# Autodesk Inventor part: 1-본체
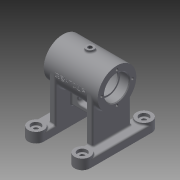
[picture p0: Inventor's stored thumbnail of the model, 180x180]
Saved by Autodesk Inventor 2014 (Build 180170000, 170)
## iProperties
Created: 2015-11
Part Number: 1-본체
Material: Generic
Document SubType Name: Modeling
Designer: test_24
Density: 1 g/cm^3
Appearance: Default
Author: test_24
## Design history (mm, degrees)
sketch "스케치1"
  geometry: L1 (-35, 25)-(35, 25); L2 (35, 25)-(35, 16); L3 (35, 0)-(-35, 0); L4 (-35, 16)-(-35, 25); L5 (-35, 16)-(-23, 16); L6 (-23, 16)-(-23, 14); L7 (-23, 14)-(-21, 14); L8 (-21, 14)-(-21, 21); L9 (-21, 21)-(21, 21); L10 (21, 21)-(21, 14); L11 (21, 14)-(23, 14); L12 (23, 14)-(23, 16); L13 (23, 16)-(35, 16); 1 further point
  constraints: 26 end point, 8 parallel, 4 perpendicular, 2 vertical alignment, 1 horizontal, 1 midpoint
  dimensions: "d0" = 25 distance of L3.end L1.start; "d1" = 70 distance of L3.start L3.end; "d2" = 35 distance from line of point (0, 0) L4; "d3" = 32 diameter of L5 L3; "d4" = 28 diameter of L7 L3; "d5" = 42 diameter of L9 L3; "d6" = 28 diameter of L11 L3; "d7" = 32 diameter of L13 L3; "d8" = 12 distance between parallel lines of L6 L4; "d9" = 2 distance between parallel lines of L6 L8; "d10" = 42 distance between parallel lines of L8 L10; "d11" = 2 distance between parallel lines of L12 L10
revolve "회전1" sketch "스케치1" stored, may be unused: angle "d12" = 90 deg
node "작업 평면1"
sketch "스케치2"
  geometry: L1 (-40, -40)-(-40, 40); L2 (-20, 40)-(-20, -40); L3 (20, -40)-(20, 40); L4 (40, 40)-(40, -40); A1 r 10 centre (-30, -40) between (-20, -40) and (-40, -40); A2 r 10 centre (-30, 40) between (-40, 40) and (-20, 40); A3 r 10 centre (30, 40) between (20, 40) and (40, 40); A4 r 10 centre (30, -40) between (40, -40) and (20, -40); 1 further point
  constraints: 8 end point, 8 point on circle, 4 centre point, 3 equal radius, 3 tangent, 2 horizontal alignment, 2 parallel, 2 vertical alignment
  dimensions: "d14" = 80 distance between parallel lines of L4 L1; "d15" = 40 distance from line of L1 point (0, 0); "d16" = 20 distance between parallel lines of L4 L3; "d17" = 20 distance between parallel lines of L1 L2; "d22" = 10 radius of A4; "d23" = 80 distance of A3.centre A4.centre; "d36" = 40 vertical distance of A4.centre point (0, 0)
extrude "돌출1" join sketch "스케치2" distance "d26" = 10; taper "d27" = 0 deg
sketch "스케치3"
  geometry: L1 (40, -40)-(40, 40) reference; L2 (-40, 40)-(-40, -40) reference; C1 r 10 at (-30, -40); C2 r 10 at (-30, 40); C3 r 10 at (30, 40); A1 r 10 centre (-30, -40) between (-20, -40) and (-40, -40) reference; A2 r 10 centre (-30, 40) between (-40, 40) and (-20, 40) reference; A3 r 10 centre (30, 40) between (20, 40) and (40, 40) reference; A4 r 10 centre (30, -40) between (40, -40) and (20, -40) reference; 2 further points
  constraints: 4 coincident, 3 centre point, 3 tangent, 1 horizontal alignment, 2 other
extrude "돌출2" join sketch "스케치3" distance "d28" = 13; taper "d29" = 0 deg
node "스케치4"
sketch "스케치5"
  geometry: L1 (20, 40)-(20, -40) reference; L2 (-20, 40)-(-20, -40) reference; L3 (20, 25)-(28, 25); L4 (28, 25)-(28, -25); L5 (28, -25)-(20, -25); L6 (20, -25)-(20, 25); L7 (-20, 25)-(-28, 25); L8 (-28, 25)-(-28, -25); L9 (-28, -25)-(-20, -25); L10 (-20, -25)-(-20, 25); 1 further point
  constraints: 16 end point, 4 parallel, 2 horizontal, 2 perpendicular, 2 point on line
  dimensions: "d37" = 8 distance of L4.end L5.end; "d38" = 50 distance of L3.end L4.end; "d39" = 8 distance of L9.end L8.end; "d40" = 50 distance of L8.end L7.end; "d41" = 25 distance from line of point (0, 0) L3; "d42" = 25 distance from line of L7 point (0, 0)
extrude "돌출3" join sketch "스케치5" stored distance "d43" = 13; taper "d44" = 0 deg
sketch "스케치6"
  geometry: L1 (-20, -58)-(-20, 0) reference; L2 (20, -22.684)-(20, -45); L3 (20, -45)-(-20, -45); L4 (-20, -45)-(-20, -22.684); L5 (-20, -22.684)-(20, -22.684); L6 (20, -58)-(20, 0) reference; L7 (-35, -25)-(35, -25) reference; 1 further point
  constraints: 8 end point, 3 collinear, 1 parallel
  dimensions: "d104" = 20 distance between parallel lines of L7 L3; "d105" = 22.31618 distance between parallel lines of L3 L5
extrude "돌출4" join sketch "스케치6" stored distance "d47" = 8; taper "d48" = 0 deg
sketch "스케치8"
  geometry: C1 r 10 at (0, 0) reference; C2 r 10 at (0, 80) reference; C3 r 10 at (60, 80) reference; C4 r 10 at (60, 0) reference; 5 further points
  constraints: 4 coincident
hole "구멍1" sketch "스케치8" at (0, 80), (60, 80), (60, 0), (0, 0) diameter "d56" = 6; stored, may be unused: countersink angle "d60" = 90 deg, drill point angle "d62" = 118 deg; dims "d57" = 6, "d58" = 12, "d59" = 4, "d61" = 8
node "작업 평면3"
sketch "스케치11"
  geometry: C1 r 5 at (0, 0); 1 further point
  constraints: 1 centre point, 1 coincident
  dimensions: "d70" = 10 diameter of C1
extrude "돌출7" join sketch "스케치11" stored distance "d71" = 8; taper "d72" = 0 deg
sketch "스케치12"
  geometry: C1 r 5 at (0, 0) reference; 1 further point
  constraints: 1 coincident
hole "구멍2" sketch "스케치12" at (0, 0) diameter "d73" = 5.188; stored, may be unused: countersink angle "d77" = 90 deg, drill point angle "d79" = 118 deg; dims "d74" = 14, "d75" = 12, "d76" = 4, "d78" = 15
fillet "모깎기1" dims "d87" = 0.3
fillet "모깎기2" dims "d88" = 3
sketch "스케치14"
  geometry: C1 r 16 at (0, 0) reference; 4 further points
  constraints: 1 vertical alignment, 5 other
  dimensions: "d89" = 20 distance of C1.centre point (0, 20); "d92" = 360 deg dimension on C1.centre point (0, 20) (derived)
hole "구멍4" sketch "스케치14" at (0, 20), (-20, 0), (0, -20), (20, 0) diameter "d94" = 3.242; stored, may be unused: countersink angle "d98" = 90 deg, drill point angle "d100" = 118 deg; dims "d95" = 8, "d96" = 12, "d97" = 4, "d99" = 10
fillet "모깎기5" dims "d103" = 2
sketch "스케치15"
  geometry: L1 (-20, -24.678)-(20, -24.678) reference; L2 (-8, -35)-(8, -35); L3 (-8, -31.5)-(8, -31.5); L4 (8, -38.5)-(-8, -38.5); L5 (20, -68)-(40, -68) reference; L6 (-35, -21.621)-(-35, -18.379) reference; A1 r 3.5 centre (-8, -35) between (-8, -31.5) and (-8, -38.5); A2 r 3.5 centre (8, -35) between (8, -38.5) and (8, -31.5); 2 further points
  constraints: 8 end point, 4 point on circle, 4 tangent, 2 centre point, 2 parallel, 1 midpoint
  dimensions: "d106" = 3.5 radius of A2; "d107" = 33 distance from line of L5 point (0, -35); "d108" = 35 distance from line of L6 point (0, -35); "d109" = 16 distance of L2.end L2.start
extrude "돌출8" cut sketch "스케치15" distance "d110" = 8; taper "d111" = 0 deg
sketch "스케치16"
  geometry: L1 (0, 0)-(-24.249, -14); L2 (0, 0)-(-23.07, 0)
  constraints: 4 end point, 1 horizontal
  dimensions: "d112" = 28 distance of L1.start L1.end; "d113" = 30 deg angle of L2 L1
node "작업 평면4"
sketch "스케치17"
  geometry: C1 r 6 at (0, 0); 1 further point
  constraints: 1 centre point, 1 coincident
  dimensions: "d114" = 12 diameter of C1
extrude "돌출9" join sketch "스케치17" stored distance "d115" = 8; taper "d116" = 0 deg
sketch "스케치18"
  geometry: C1 r 6 at (0, 0) reference; 1 further point
  constraints: 1 coincident
hole "구멍5" sketch "스케치18" at (0, 0) diameter "d117" = 5.188; stored, may be unused: countersink angle "d121" = 90 deg, drill point angle "d123" = 118 deg; dims "d118" = 8, "d119" = 12, "d120" = 4, "d122" = 10
fillet "모깎기6" dims "d124" = 2
fillet "모깎기7" dims "d125" = 2
fillet "모깎기8" dims "d126" = 2
fillet "모깎기9" dims "d127" = 2
chamfer "모따기1" distance "d128" = 1; stored, may be unused: second distance "d129" = 2, angle "d130" = 45 deg
fillet "모깎기10" dims "d131" = 2
fillet "모깎기11" dims "d132" = 2
node "작업 평면5"
sketch "스케치19"
  geometry: L1 (-35, -25)-(-35, 25) reference; L2 (-35, 25)-(35, 25) reference; 2 further points
  constraints: 1 other
  dimensions: "d134" = 35 distance from line of point (0, 0) L1; "d135" = 25 distance from line of L2 point (0, 0)
feature "엠보싱1" sketch "스케치19" dims "d136" = 0.5, "d137" = 0
fillet "모깎기12" dims "d138" = 0.3
node "솔리드1"
mirror "대칭1"
other parameters: "d13" = -68, "d69" = 28, "d133" = 25.5
